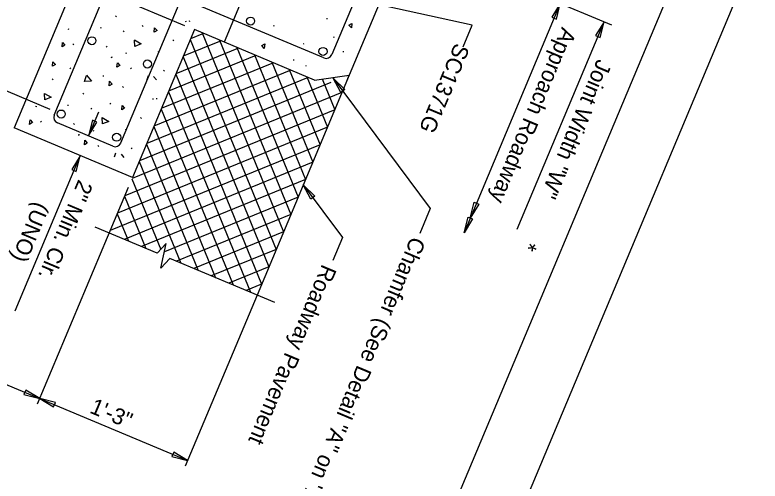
# Model space of a CAD drawing. Extents: x 1968564 to 1968711, y 796599 to 796794.
# Drawn here: x 1968652.64 to 1968675.87, y 796655.71 to 796670.24 of the extents above; entities that cross this region are included whole.
import ezdxf

# ---------------------------------------------------------------- set-up
doc = ezdxf.new("R2010")
doc.units = 0
for name, color, linetype in [('BR_AUTO DIMENSION', 7, 'Continuous'), ('BR_BORDER LINES', 7, 'Continuous'), ('BR_CONCRETE', 7, 'Continuous'), ('BR_DETAILS', 7, 'Continuous'), ('BR_REBAR', 7, 'Continuous'), ('BR_TABLE LINES', 7, 'Continuous'), ('BR_TEXT', 7, 'Continuous'), ('Level 31', 7, 'Continuous')]:
    doc.layers.add(name, color=color, linetype=linetype)

# ---------------------------------------------------------------- blocks, each defined once
blk = doc.blocks.new('B')
at = {"layer": 'BR_AUTO DIMENSION'}
blk.add_lwpolyline([(-0.2, 0.03), (0, 0), (-0.2, -0.03)], close=True, dxfattribs=at)
blk = doc.blocks.new('ARROW')
at = {"layer": 'BR_AUTO DIMENSION', "xscale": 0.625, "yscale": 0.625}
blk.add_blockref('B', (0, 0), dxfattribs=at)
blk = doc.blocks.new('DAH')
at = {"layer": 'BR_AUTO DIMENSION'}
for p in [(-0.1248, 0), (0, 0)]:
    blk.add_blockref('ARROW', p, dxfattribs=at)

msp = doc.modelspace()

# ---------------------------------------------------------------- linework, layer by layer
at = {"layer": 'BR_AUTO DIMENSION'}
for p, q in [((1968664.926, 796672.582), (1968671.236, 796669.935)), ((1968653.729, 796671.675), (1968657.933, 796669.912)), ((1968666.9, 796669.924), (1968663.245, 796670.729)), ((1968669.646, 796670.602), (1968666.647, 796663.451)), ((1968668.297, 796663.562), (1968671.01, 796670.03)), ((1968666.615, 796669.245), (1968666.9, 796669.924)), ((1968653.746, 796667.296), (1968651.527, 796668.227)), ((1968662.57, 796668.27), (1968665.586, 796664.205)), ((1968655.249, 796667.206), (1968654.94, 796666.468)), ((1968652.652, 796661.013), (1968654.682, 796665.853)), ((1968661.633, 796664.947), (1968662.855, 796663.301)), ((1968656.174, 796664.858), (1968653.342, 796658.106)), ((1968665.586, 796664.205), (1968665.262, 796663.432)), ((1968662.855, 796663.301), (1968662.557, 796662.591)), ((1968660.192, 796661.509), (1968657.953, 796656.172)), ((1968649.728, 796659.831), (1968658.028, 796656.35))]:
    msp.add_line(p, q, dxfattribs=at)
for points in [[(1968669.522, 796670.112), (1968669.646, 796670.602), (1968669.384, 796670.17)], [(1968670.885, 796669.54), (1968671.01, 796670.03), (1968670.747, 796669.598)], [(1968662.807, 796667.824), (1968662.57, 796668.27), (1968662.928, 796667.913)], [(1968655.064, 796666.958), (1968654.94, 796666.468), (1968655.203, 796666.9)], [(1968654.558, 796665.363), (1968654.682, 796665.853), (1968654.42, 796665.421)], [(1968661.871, 796664.5), (1968661.633, 796664.947), (1968661.992, 796664.59)], [(1968652.927, 796658.408), (1968653.417, 796658.283), (1968652.985, 796658.546)], [(1968653.907, 796658.159), (1968653.417, 796658.283), (1968653.849, 796658.021)], [(1968657.538, 796656.474), (1968658.028, 796656.35), (1968657.596, 796656.612)]]:
    msp.add_lwpolyline(points, close=True, dxfattribs=at)
at = {"layer": 'BR_BORDER LINES'}
msp.add_line((1968643.927, 796601.539), (1968696.012, 796725.723), dxfattribs=at)
at = {"layer": 'BR_CONCRETE'}
for p, q in [((1968658.419, 796680.552), (1968652.617, 796666.719)), ((1968664.752, 796672.383), (1968663.068, 796668.368)), ((1968659.807, 796670.933), (1968659.162, 796669.396)), ((1968658.24, 796669.783), (1968656.306, 796665.172)), ((1968661.986, 796668.212), (1968658.24, 796669.783)), ((1968661.986, 796668.212), (1968663.068, 796668.368)), ((1968656.306, 796665.172), (1968652.617, 796666.719))]:
    msp.add_line(p, q, dxfattribs=at)
at = {"layer": 'BR_DETAILS'}
for p, q in [((1968655.778, 796670.215), (1968655.806, 796670.185)), ((1968657.979, 796670.035), (1968657.95, 796670.029)), ((1968658.093, 796670.043), (1968658.064, 796670.037)), ((1968662.358, 796670.128), (1968662.388, 796670.134)), ((1968654.34, 796669.79), (1968654.304, 796669.801)), ((1968655.331, 796669.838), (1968655.302, 796669.833)), ((1968656.612, 796669.91), (1968656.64, 796669.881)), ((1968660.709, 796669.902), (1968660.739, 796669.908)), ((1968656.02, 796669.748), (1968656.049, 796669.718)), ((1968654.45, 796669.341), (1968654.478, 796669.311)), ((1968657.571, 796669.463), (1968657.599, 796669.433)), ((1968661.636, 796669.341), (1968661.665, 796669.347)), ((1968662.577, 796669.549), (1968662.607, 796669.555)), ((1968655.485, 796669.268), (1968655.513, 796669.239)), ((1968662.869, 796669.098), (1968662.899, 796669.104)), ((1968655.659, 796668.911), (1968655.63, 796668.905)), ((1968655.674, 796668.923), (1968655.645, 796668.917)), ((1968656.133, 796669.038), (1968656.097, 796669.049)), ((1968657.124, 796669.086), (1968657.095, 796669.081)), ((1968661.316, 796668.84), (1968661.345, 796668.846)), ((1968654.353, 796668.593), (1968654.381, 796668.564)), ((1968656.243, 796668.589), (1968656.271, 796668.559)), ((1968657.278, 796668.516), (1968657.306, 796668.486)), ((1968653.806, 796668.247), (1968653.834, 796668.217)), ((1968655.417, 796668.334), (1968655.388, 796668.328)), ((1968656.763, 796668.231), (1968656.804, 796668.358)), ((1968656.969, 796668.318), (1968657.054, 796668.215)), ((1968656.001, 796668.012), (1968656.029, 796667.982)), ((1968654.765, 796667.799), (1968654.793, 796667.77)), ((1968655.599, 796667.495), (1968655.627, 796667.465)), ((1968656.966, 796667.619), (1968656.936, 796667.614)), ((1968657.08, 796667.627), (1968657.051, 796667.621)), ((1968653.327, 796667.375), (1968653.291, 796667.385)), ((1968654.318, 796667.423), (1968654.288, 796667.417)), ((1968655.007, 796667.332), (1968655.035, 796667.302)), ((1968656.558, 796667.047), (1968656.586, 796667.018)), ((1968653.437, 796666.925), (1968653.465, 796666.896)), ((1968654.472, 796666.853), (1968654.5, 796666.823)), ((1968655.12, 796666.623), (1968655.084, 796666.633)), ((1968656.111, 796666.671), (1968656.082, 796666.665)), ((1968654.646, 796666.495), (1968654.616, 796666.489)), ((1968654.661, 796666.507), (1968654.632, 796666.501)), ((1968655.23, 796666.173), (1968655.258, 796666.144)), ((1968656.265, 796666.101), (1968656.293, 796666.071)), ((1968655.749, 796665.816), (1968655.79, 796665.942)), ((1968655.956, 796665.902), (1968656.04, 796665.799)), ((1968657.076, 796662.816), (1968655.142, 796663.627)), ((1968660.748, 796661.276), (1968657.477, 796662.648))]:
    msp.add_line(p, q, dxfattribs=at)
for points in [[(1968656.999, 796669.837), (1968657.076, 796669.751), (1968656.986, 796669.699), (1968656.999, 796669.837)], [(1968663.135, 796669.836), (1968663.058, 796669.922), (1968663.148, 796669.975), (1968663.135, 796669.836)], [(1968654.129, 796669.386), (1968654.205, 796669.3), (1968654.115, 796669.247), (1968654.129, 796669.386)], [(1968656.377, 796669.46), (1968656.583, 796669.338), (1968656.384, 796669.26), (1968656.376, 796669.456)], [(1968660.418, 796669.2), (1968660.341, 796669.286), (1968660.431, 796669.339), (1968660.418, 796669.2)], [(1968653.831, 796668.782), (1968653.908, 796668.696), (1968653.818, 796668.643), (1968653.831, 796668.782)], [(1968655.837, 796668.75), (1968655.914, 796668.664), (1968655.824, 796668.612), (1968655.837, 796668.75)], [(1968654.879, 796668.361), (1968655.031, 796668.175), (1968654.817, 796668.17), (1968654.877, 796668.357)], [(1968655.595, 796668.174), (1968655.672, 796668.087), (1968655.582, 796668.035), (1968655.595, 796668.174)], [(1968653.57, 796667.796), (1968653.777, 796667.674), (1968653.577, 796667.596), (1968653.57, 796667.792)], [(1968655.986, 796667.422), (1968656.063, 796667.335), (1968655.973, 796667.283), (1968655.986, 796667.422)], [(1968655.364, 796667.044), (1968655.57, 796666.922), (1968655.371, 796666.844), (1968655.363, 796667.04)], [(1968653.115, 796666.97), (1968653.192, 796666.884), (1968653.102, 796666.831), (1968653.115, 796666.97)], [(1968654.824, 796666.335), (1968654.9, 796666.248), (1968654.811, 796666.196), (1968654.824, 796666.335)], [(1968657.477, 796662.648), (1968657.194, 796662.348), (1968657.359, 796663.116), (1968657.076, 796662.816)]]:
    msp.add_lwpolyline(points, dxfattribs=at)
at = {"layer": 'BR_REBAR'}
for p, q in [((1968653.87, 796667.12), (1968659.011, 796679.377)), ((1968655.945, 796666.25), (1968661.041, 796678.401)), ((1968663.731, 796671.886), (1968662.522, 796669.004)), ((1968662.277, 796668.903), (1968655.636, 796671.689)), ((1968655.699, 796666.149), (1968653.97, 796666.874))]:
    msp.add_line(p, q, dxfattribs=at)
for centre in [(1968659.99, 796670.049), (1968655.045, 796669.437), (1968662.248, 796669.102), (1968656.774, 796668.712), (1968654.087, 796667.153), (1968655.816, 796666.428)]:
    msp.add_circle(centre, 0.125, dxfattribs=at)
for centre, start, end in [((1968662.349, 796669.076), 247.246, 337.246), ((1968654.043, 796667.047), 157.246, 247.246), ((1968655.772, 796666.322), 247.246, 337.246)]:
    msp.add_arc(centre, 0.188, start, end, dxfattribs=at)
at = {"layer": 'BR_TABLE LINES'}
for p, q in [((1968658.528, 796669.662), (1968658.119, 796669.495)), ((1968658.479, 796669.683), (1968661.017, 796663.477)), ((1968659.072, 796669.434), (1968657.891, 796668.951)), ((1968658.112, 796669.479), (1968660.789, 796662.934)), ((1968659.022, 796669.455), (1968661.245, 796664.021)), ((1968659.615, 796669.206), (1968657.663, 796668.408)), ((1968659.566, 796669.227), (1968661.473, 796664.564)), ((1968660.159, 796668.978), (1968657.435, 796667.865)), ((1968657.884, 796668.935), (1968660.561, 796662.391)), ((1968660.109, 796668.999), (1968661.701, 796665.108)), ((1968660.702, 796668.751), (1968657.207, 796667.321)), ((1968660.653, 796668.771), (1968661.929, 796665.651)), ((1968661.708, 796668.658), (1968661.738, 796668.664)), ((1968661.245, 796668.523), (1968656.979, 796666.778)), ((1968661.196, 796668.543), (1968662.157, 796666.194)), ((1968661.789, 796668.295), (1968656.752, 796666.234)), ((1968657.656, 796668.392), (1968660.333, 796661.847)), ((1968663.068, 796668.368), (1968660.192, 796661.509)), ((1968661.739, 796668.315), (1968662.385, 796666.738)), ((1968662.218, 796668.245), (1968662.613, 796667.281)), ((1968662.968, 796668.129), (1968663.068, 796668.368)), ((1968662.491, 796668.132), (1968656.524, 796665.691)), ((1968662.84, 796667.825), (1968656.296, 796665.148)), ((1968657.429, 796667.849), (1968659.986, 796661.596)), ((1968662.613, 796667.281), (1968656.068, 796664.604)), ((1968657.201, 796667.305), (1968659.443, 796661.824)), ((1968662.385, 796666.738), (1968655.84, 796664.061)), ((1968656.973, 796666.762), (1968658.899, 796662.051)), ((1968662.157, 796666.194), (1968655.612, 796663.517)), ((1968656.745, 796666.218), (1968658.356, 796662.279)), ((1968661.929, 796665.651), (1968656.05, 796663.246)), ((1968656.517, 796665.675), (1968657.813, 796662.507)), ((1968656.289, 796665.132), (1968657.188, 796662.934)), ((1968661.701, 796665.108), (1968656.594, 796663.019)), ((1968656.061, 796664.588), (1968656.726, 796662.963)), ((1968661.473, 796664.564), (1968657.304, 796662.859)), ((1968655.833, 796664.045), (1968656.182, 796663.191)), ((1968661.245, 796664.021), (1968657.68, 796662.563)), ((1968661.017, 796663.477), (1968658.224, 796662.335)), ((1968660.789, 796662.934), (1968658.767, 796662.107)), ((1968660.561, 796662.391), (1968659.311, 796661.879)), ((1968660.333, 796661.847), (1968659.854, 796661.651))]:
    msp.add_line(p, q, dxfattribs=at)
at = {"layer": 'Level 31'}
msp.add_lwpolyline([(1968619.541, 796765.748), (1968563.846, 796632.955), (1968644.997, 796598.919), (1968700.693, 796731.712)], close=True, dxfattribs=at)

# ---------------------------------------------------------------- block references
at = {"layer": 'BR_TEXT', "xscale": 4.000000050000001, "yscale": 4.00000005, "rotation": -112.75398965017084}
msp.add_blockref('DAH', (1968666.647, 796663.451), dxfattribs=at)

# ---------------------------------------------------------------- texts
at = {"layer": 'BR_AUTO DIMENSION'}
for s, rotation, p in [('Joint Width "W"', 247.246, (1968670.802, 796668.888)), ('2" Min. Clr. ', 247.246, (1968654.628, 796665.135)), ('(UNO)', 247.246, (1968653.275, 796664.445)), ('1\'-3"', 337.246, (1968654.946, 796657.851))]:
    msp.add_text(s, height=0.5, rotation=rotation, dxfattribs=at).set_placement(p)
at = {"layer": 'BR_TEXT'}
for s, height, p in [('Approach Roadway', 0.49995, (1968669.697, 796669.886)), (' SC1371G', 0.4999, (1968666.441, 796669.565)), ('Chamfer (See Detail "A" on "Approach Slab No. 3" sheet)', 0.49995, (1968665.001, 796663.364)), ('*', 0.5, (1968668.482, 796663.252)), ('Roadway Pavement', 0.49995, (1968662.226, 796662.496))]:
    msp.add_text(s, height=height, rotation=247.246, dxfattribs=at).set_placement(p)

doc.saveas('drawing.dxf')
